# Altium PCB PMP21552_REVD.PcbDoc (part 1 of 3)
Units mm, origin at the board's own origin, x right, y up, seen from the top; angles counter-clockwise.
Board outline 45.05 x 86.02 mm, 4 copper layers (Top Layer, Signal Layer 1, Signal Layer 2, Bottom Layer), stack 1.006 mm thick; 146 components, 80 nets, 395 pads, 82 vias.
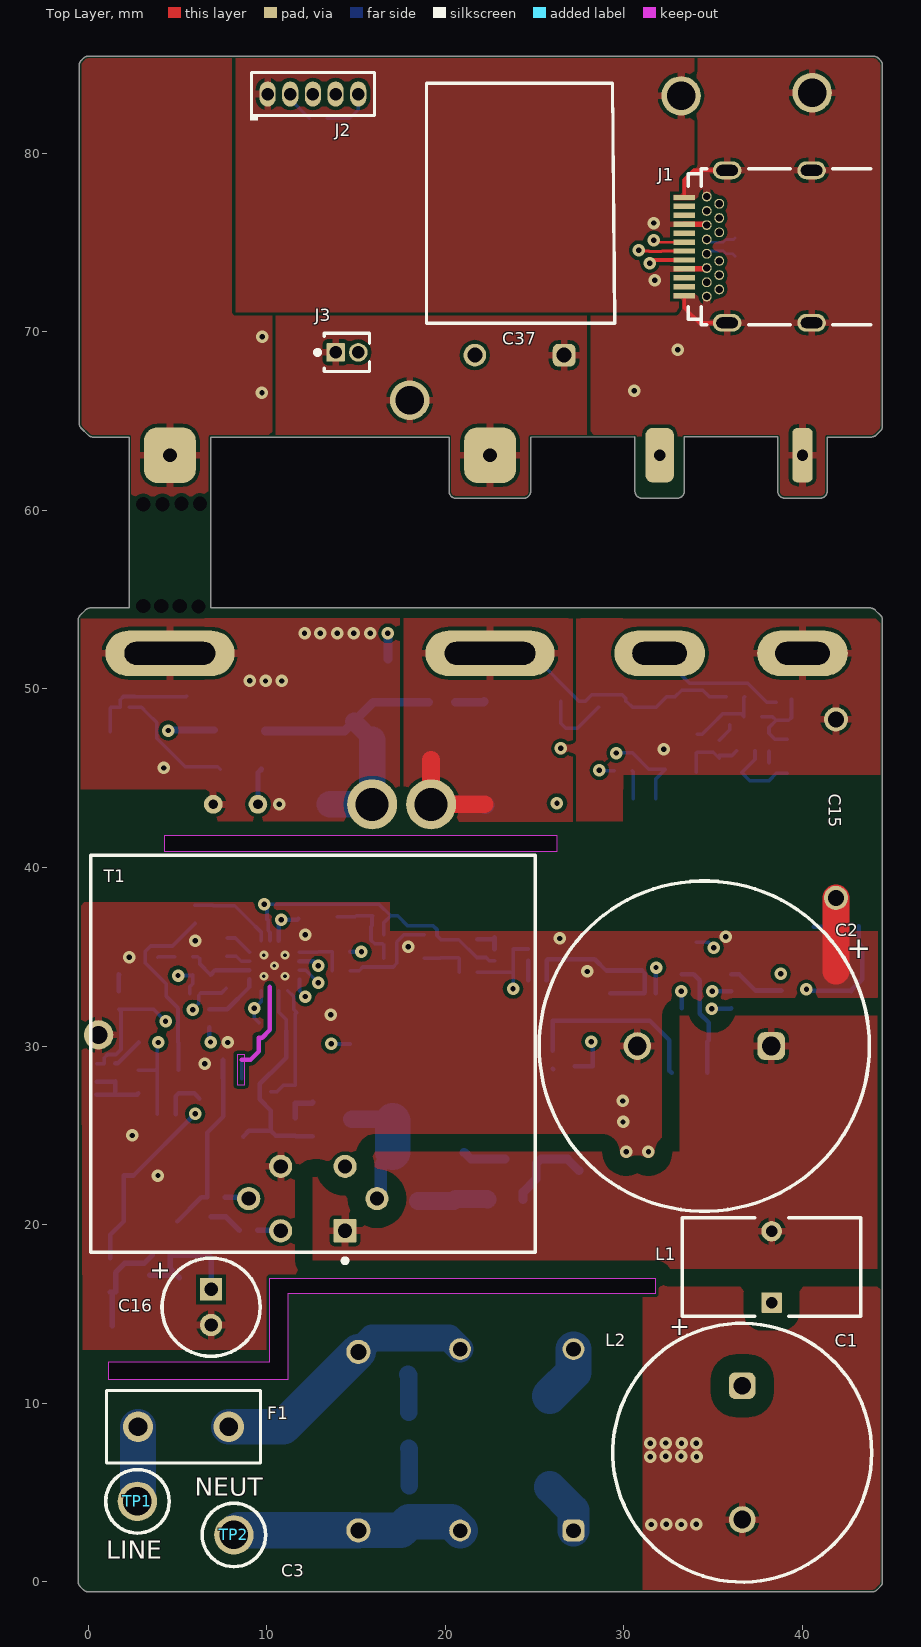
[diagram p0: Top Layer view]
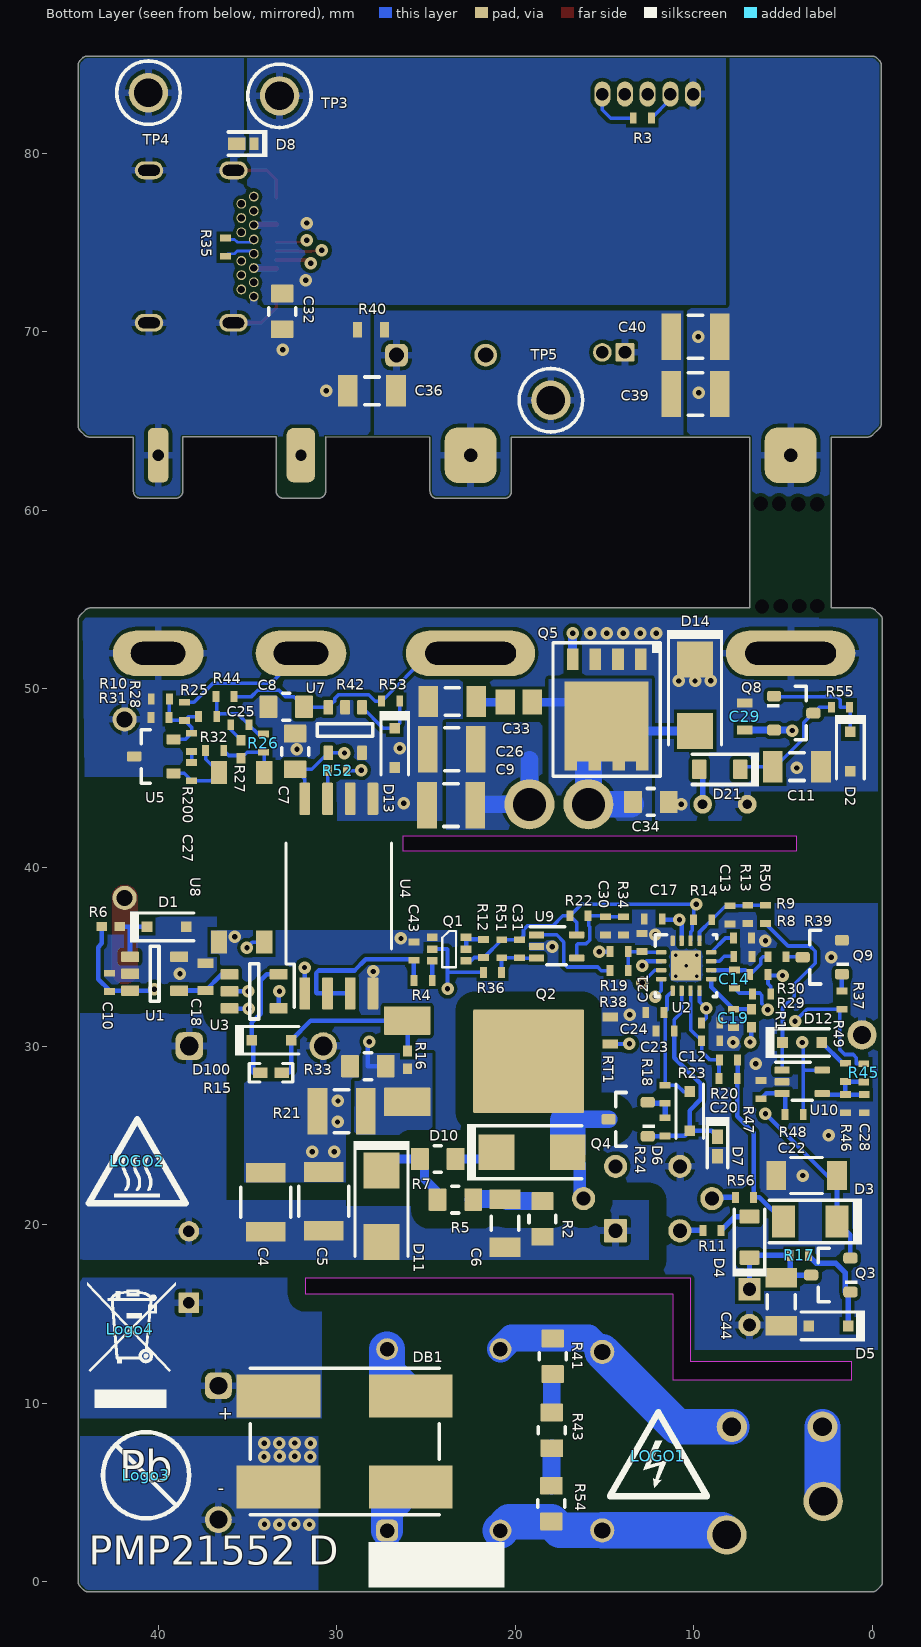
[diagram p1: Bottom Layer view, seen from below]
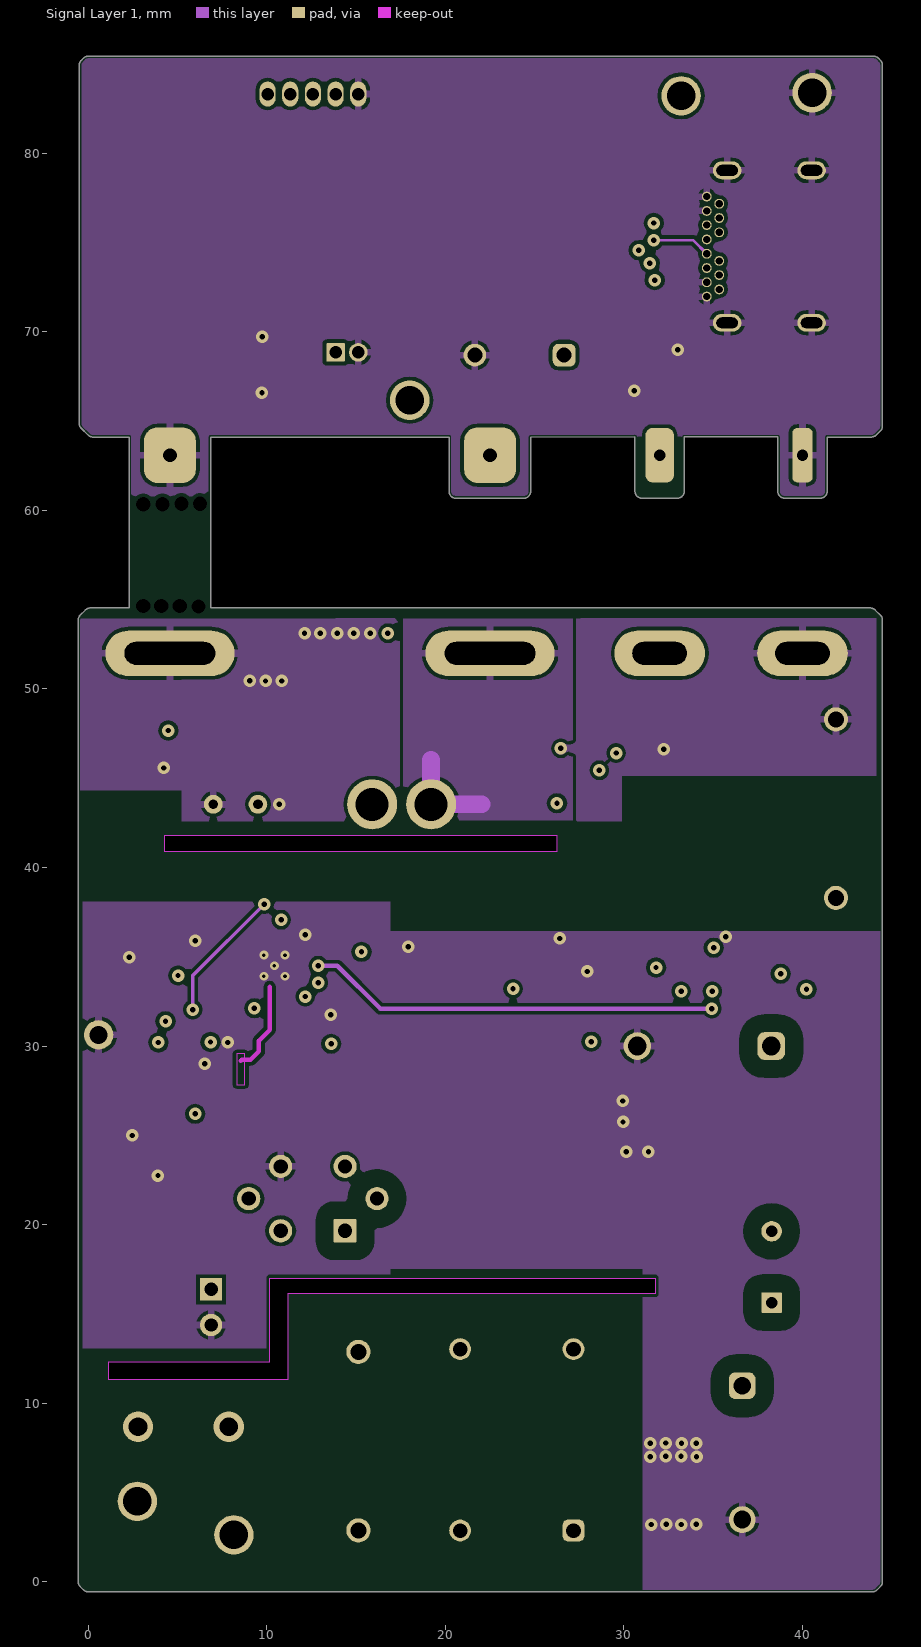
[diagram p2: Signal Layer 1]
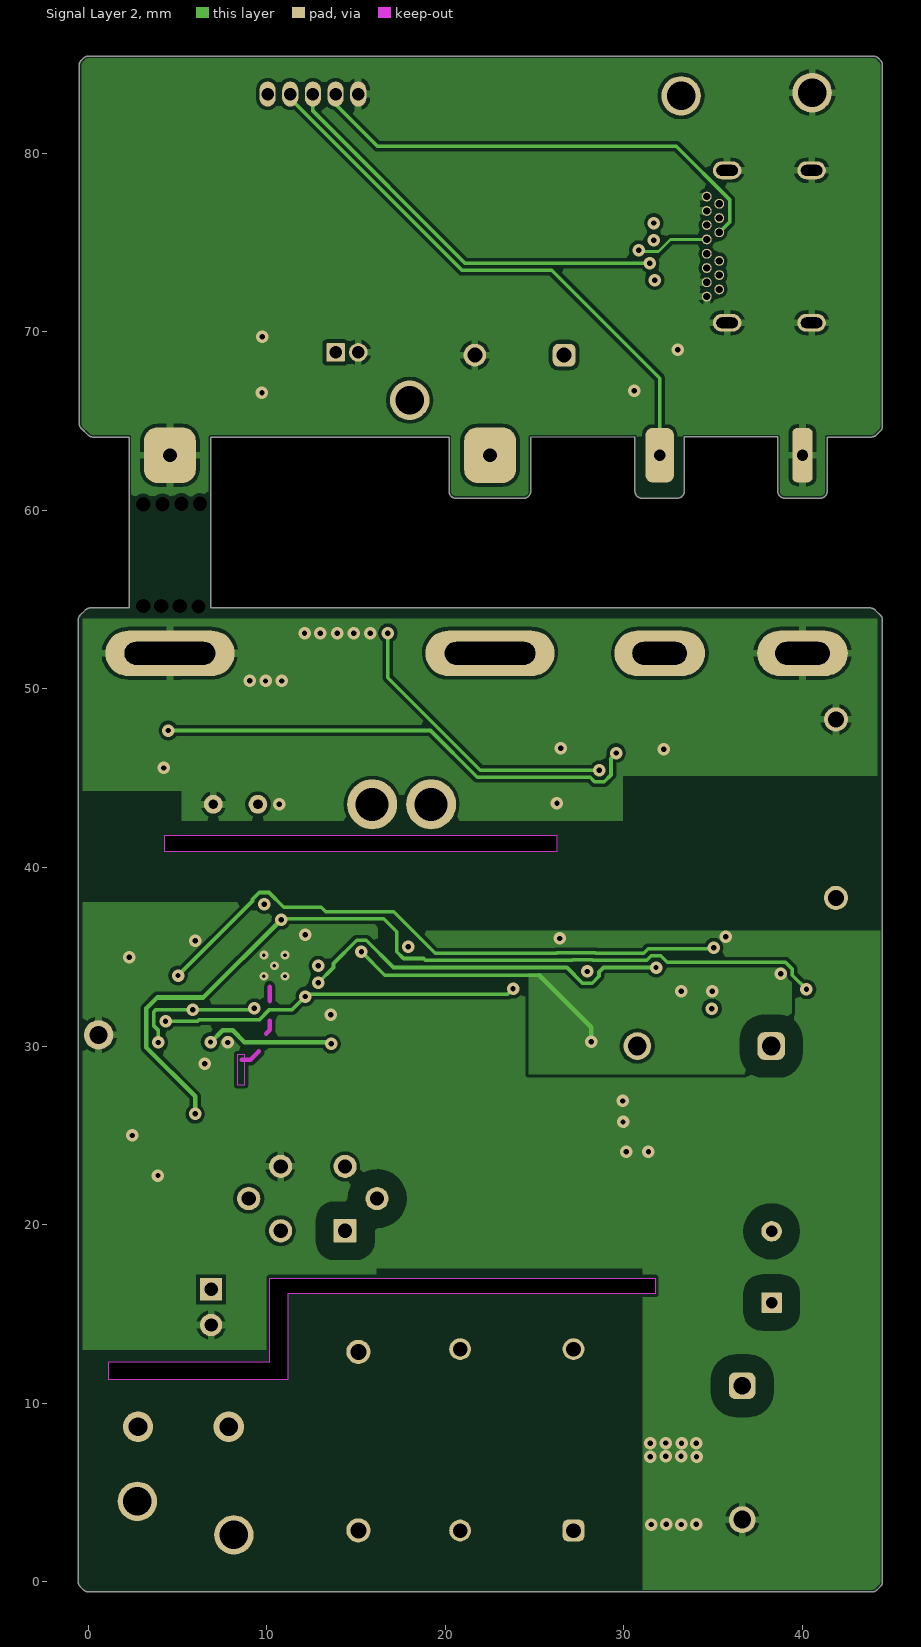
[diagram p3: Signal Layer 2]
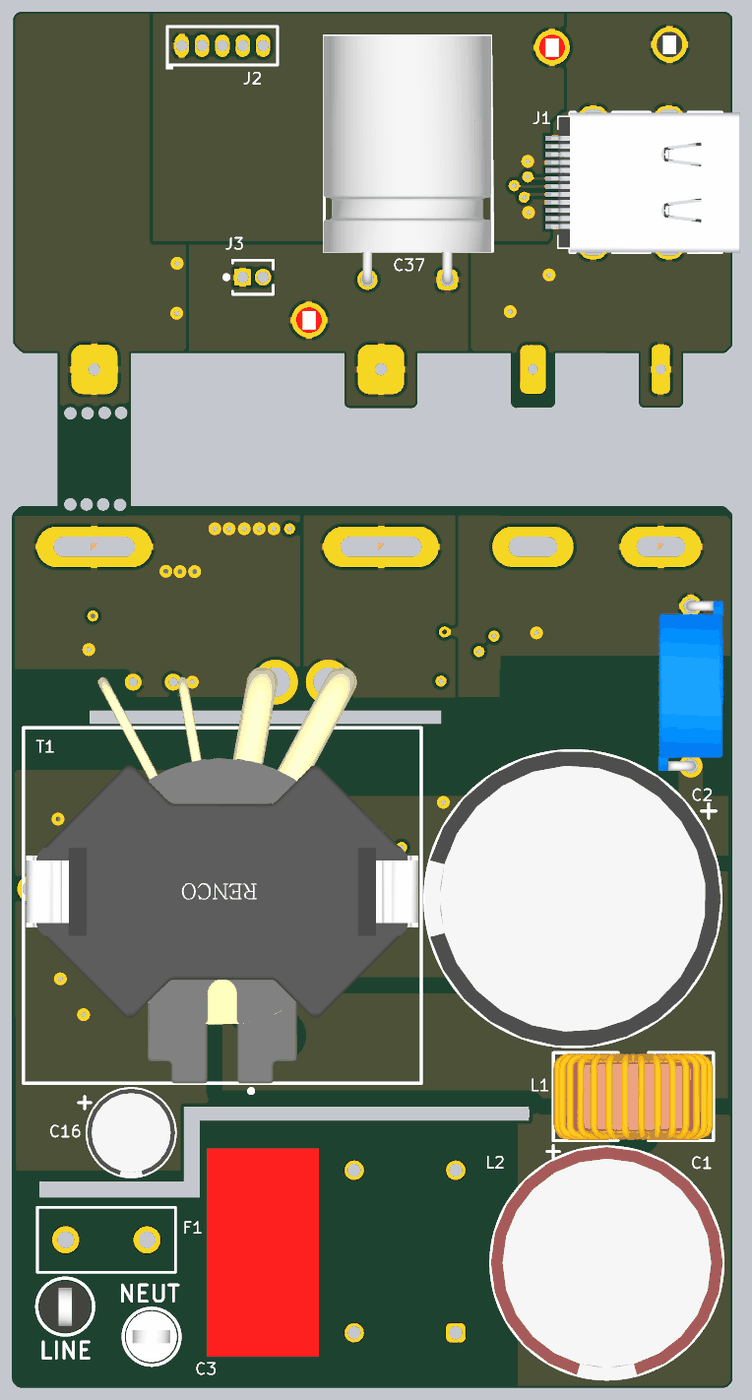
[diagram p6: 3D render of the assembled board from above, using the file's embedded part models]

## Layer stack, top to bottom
Top Solder: solder mask 0.0102, Solder Resist, Dk 3.5
Top Layer: signal copper 0.0356
Dielectric 1: prepreg 0.2032, FR-4, Dk 4.2
Signal Layer 1: signal copper 0.0356
Dielectric 2: core 0.4572, FR-4, Dk 4.2
Signal Layer 2: signal copper 0.0356
Dielectric 3: prepreg 0.2032, FR-4, Dk 4.2
Bottom Layer: signal copper 0.0356
Bottom Solder: solder mask 0.0102, Solder Resist, Dk 3.5

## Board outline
-0.573,0 -0.573,53.858 -0.573,53.862 cw(c-0.191,53.858) -0.463,54.126 -0.461,54.128 -0.16,54.429 -0.159,54.43 cw(c0.11,54.159) 0.11,54.541 2.285,54.541 2.285,64.111 0.254,64.111 cw(c0.254,64.493) -0.014,64.221 -0.016,64.223 -0.397,64.604 -0.399,64.606 cw(c-0.127,64.874) -0.509,64.874 -0.509,84.94 cw(c-0.127,84.94) -0.398,85.209 -0.397,85.21 -0.27,85.337 -0.269,85.338 cw(c0,85.067) 0,85.449 43.973,85.449 cw(c43.973,85.067) 44.242,85.338 44.243,85.337 44.37,85.21 44.371,85.209 cw(c44.1,84.94) 44.482,84.94 44.482,64.734 cw(c44.1,64.734) 44.371,64.466 44.37,64.464 44.128,64.223 44.127,64.221 cw(c43.858,64.493) 43.858,64.111 41.382,64.114 41.382,61.07 cw(c41,61.07) 41,60.688 39,60.688 cw(c39,61.07) 38.618,61.07 38.618,64.117 33.382,64.123 33.382,61.07 cw(c33,61.07) 33,60.688 31.04,60.688 31.023,60.689 cw(c31,61.07) 30.618,61.07 30.618,64.117 24.772,64.111 24.772,61.064 cw(c24.39,61.064) 24.39,60.682 20.59,60.682 cw(c20.59,61.064) 20.208,61.064 20.208,64.111 6.859,64.111 6.859,54.541 43.799,54.541 cw(c43.799,54.159) 44.068,54.431 44.069,54.429 44.37,54.128 44.371,54.127 cw(c44.1,53.858) 44.482,53.858 44.482,0 cw(c44.1,0) 44.371,-0.269 44.37,-0.27 44.179,-0.461 44.178,-0.462 cw(c43.909,-0.191) 43.909,-0.573 0,-0.573 cw(c0,-0.191) -0.269,-0.462 -0.27,-0.461 -0.461,-0.27 -0.462,-0.269 cw(c-0.191,0)
cut-out: 4.264,41.775 4.264,40.925 26.264,40.925 26.264,41.775
cut-out: 1.143,11.303 1.143,12.319 10.16,12.319 10.16,17 31.75,17 31.75,16.125 11.176,16.125 11.176,11.303

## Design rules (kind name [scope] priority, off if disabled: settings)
AcuteAngle [All] p1: minimum=5.00000000000000E+0000 checktracksonly=FALSE
AssemblyTestPointUsage [All] p1: valid=2
BoardOutlineClearance BoardOutlineClearance_MountingHoles [OnCopper and InComponentClass('Mounting Holes')] p1: gap=0.635 ignorepadtopadclearanceinfootprint=FALSE
BoardOutlineClearance BoardOutlineClearance_Poly [OnCopper and InPoly] p2: gap=0.1 ignorepadtopadclearanceinfootprint=FALSE
BoardOutlineClearance [OnCopper and Not InComponentClass('Logo') and not InComponentClass('FiducialMark') and not InRegion(1000,500,4000,800)] p3: gap=0.115 ignorepadtopadclearanceinfootprint=FALSE
Clearance Clearance_HV [InNetClass('HV')] p1: gap=1 ignorepadtopadclearanceinfootprint=TRUE // 1mm Clearance
Clearance Clearance_Keepouts [((IsTrack Or IsArc) And Not InPoly) And IsFree and IsKeepOut vs ((IsTrack Or IsArc) And Not InPoly) And IsFree and IsKeepOut] p2: gap=0 ignorepadtopadclearanceinfootprint=FALSE
Clearance Clearance_Poly [InPolygon] p3: gap=0.203 ignorepadtopadclearanceinfootprint=FALSE except(0: Arc-Hole Track-Hole SMDPad-Hole THPad-Hole Via-Hole Fill-Hole Poly-Hole Region-Hole Text-Hole)
Clearance [All] p4: gap=0.2 ignorepadtopadclearanceinfootprint=FALSE except(0: Arc-Hole Track-Hole SMDPad-Hole THPad-Hole Via-Hole Fill-Hole Poly-Hole Region-Hole Text-Hole)
ComponentClearance ComponentClearance_MountingHoles_FiducialMarks [InComponentClass('Mounting Holes') vs InComponentClass('FiducialMark')] p1: gap=1.27 collisioncheckmode=3 verticalgap=0.254 showdistances=FALSE
ComponentClearance ComponentClearance_Shunt [InComponentClass('Header') vs InComponentClass('Shunt')] p2: gap=0 collisioncheckmode=3 verticalgap=0 showdistances=FALSE
ComponentClearance ComponentClearance_Logo [InComponentClass('Logo')] p3: gap=1.27 collisioncheckmode=3 verticalgap=0.254 showdistances=FALSE
ComponentClearance ComponentClearance_ScrewToNut [(HasFootprint('NY PMS 440 0025 PH')) vs (HasFootprint('Keystone_1902C'))] p4: gap=0.127 collisioncheckmode=3 verticalgap=0.254 showdistances=FALSE
ComponentClearance ComponentClearance_MountingHoles [InComponentClass('Mounting Holes')] p5: gap=6.35 collisioncheckmode=3 verticalgap=2540 showdistances=FALSE
ComponentClearance ComponentClearance_SmallPassives [HasFootprint('0201*') or HasFootprint('0402*') or HasFootprint('0508') or HasFootprint('0603*') or HasFootprint('0612') or HasFootprint('0805*') or HasFootprint('0815*') or HasFootprint('0830*') or HasFootprint('1206*') or HasFootprint('1210*') or HasFootprint('1808*') or HasFootprint('1812*') or HasFootprint('1825*') or HasFootprint('2010*') or HasFootprint('2220*') or HasFootprint('2225*') or HasFootprint('2512*') or HasFootprint('2728*') or HasFootprint('3518*') vs HasFootprint('0201*') or HasFootprint('0402*') or HasFootprint('0508') or HasFootprint('0603*') or HasFootprint('0612') or HasFootprint('0805*') or HasFootprint('0815*') or HasFootprint('0830*') or HasFootprint('1206*') or HasFootprint('1210*') or HasFootprint('1808*') or HasFootprint('1812*') or HasFootprint('1825*') or HasFootprint('2010*') or HasFootprint('2220*') or HasFootprint('2225*') or HasFootprint('2512*') or HasFootprint('2728*') or HasFootprint('3518*')] p6: gap=0.38 collisioncheckmode=3 verticalgap=0.254 showdistances=FALSE
ComponentClearance ComponentClearance_THtoSMT [IsThruComponent vs IsSMTComponent] p7: gap=0.381 collisioncheckmode=3 verticalgap=0.762 showdistances=FALSE
ComponentClearance ComponentClearance_THtoTH [IsThruComponent vs IsThruComponent] p8: gap=0.381 collisioncheckmode=3 verticalgap=0.762 showdistances=FALSE
ComponentClearance [All] p9: gap=0.381 collisioncheckmode=3 verticalgap=0.254 showdistances=FALSE
DiffPairsRouting [All] p1: maxlimit=2.54 minlimit=0.254 mostfreqgap=0.254 toplayer_minwidth=0.381 toplayer_maxwidth=0.381 toplayer_prefwidth=0.381 midlayer1_minwidth=0.381 midlayer1_maxwidth=0.381 midlayer1_prefwidth=0.381 midlayer2_minwidth=0.381 midlayer2_maxwidth=0.381 midlayer2_prefwidth=0.381 bottomlayer_minwidth=0.381 bottomlayer_maxwidth=0.381 bottomlayer_prefwidth=0.381 maxuncoupledlength=25.4
FabricationTestPointUsage TestPointUsage [All] p1: valid=2 allowmultiple=FALSE
FabricationTestpoint Testpoint [All] p1: side=3 testpointundercomponent=TRUE minsize=1.016 maxsize=2.54 preferedsize=1.524 minholesize=0 maxholesize=1.016 preferedholesize=0.813 testpointgrid=0.025 allowsidetop=TRUE allowsidebottom=TRUE usegrid=TRUE gridtolerance=0
FanoutControl Fanout_LCC [IsLCC] p1: bgadir=Out bgaviamode=Centered fanoutstyle=Auto fanoutdirection=Alternating viagrid=0.025 // Fanout_LCC (Default Rule)
FanoutControl Fanout_BGA [IsBGA] p2: bgadir=Out bgaviamode=Centered fanoutstyle=Auto fanoutdirection=Alternating viagrid=0.025 // Fanout_BGA (Default Rule)
FanoutControl Fanout_Default [All] p4: bgadir=Out bgaviamode=Centered fanoutstyle=Auto fanoutdirection=Alternating viagrid=0.025 // Fanout_Default (Default Rule)
FanoutControl Fanout_Small [(CompPinCount < 5)] p5: bgadir=Out bgaviamode=Centered fanoutstyle=Auto fanoutdirection=OutThenIn viagrid=0.025 // Fanout_Small (Default Rule)
HoleSize [All] p1: absolutevalues=TRUE maxlimit=6.375 minlimit=0.2 maxpercent=80.000 minpercent=20.000
HoleToHoleClearance [All] p1: gap=0.2 allowstackedmicrovias=TRUE
MinimumAnnularRing MinimumAnnularRing_ThermalPadVias [IsVia and InAnyComponent] p1: minimumring=0.15
MinimumAnnularRing [All] p2: minimumring=0.15
MinimumSolderMaskSliver MinimumSolderMaskSliver_Logo [InComponentClass('Logo') vs InComponentClass('Logo')] p1: minsoldermaskwidth=0.018
MinimumSolderMaskSliver [All] p2: minsoldermaskwidth=0.025
PlaneConnect [All] p1: planeconnectstyle=Direct reliefexpansion=0.254 reliefentries=4 reliefconductorwidth=0.254 reliefairgap=0.254
PolygonConnect [All] p1: thpad.connectstyle=Relief thpad.reliefconductorwidth=0.4 thpad.reliefentries=4 thpad.polygonreliefangle="90 Angle" thpad.airgapwidth=0.2 smdpad.connectstyle=Direct smdpad.reliefconductorwidth=0.254 smdpad.reliefentries=4 smdpad.polygonreliefangle="90 Angle" smdpad.airgapwidth=0.254 via.connectstyle=Direct via.reliefconductorwidth=0.254 via.reliefentries=4 via.polygonreliefangle="90 Angle" via.airgapwidth=0.254
RoutingVias ThermalPadVias [IsVia and InAnyComponent] p1: holewidth=0.2 width=0.5 viastyle="Through Hole" minholewidth=0.2 minwidth=0.5 maxholewidth=0.33 maxwidth=0.6
RoutingVias [All] p2: holewidth=0.406 width=0.864 viastyle="Through Hole" minholewidth=0.2 minwidth=0.66 maxholewidth=1.016 maxwidth=1.651
SilkToBoardRegionClearance [Not ((IsComment or IsDesignator) And (Hide <> 'False')) and not InRegion(1000,500,4000,800)] p1:
SilkToSilkClearance SilkToSilkClearance_Pb-FreeLogo [(HasFootprint('Pb-Free_Overlay_Medium') OR HasFootprint('Pb-Free_Overlay_Small')) vs (HasFootprint('Pb-Free_Overlay_Medium') OR HasFootprint('Pb-Free_Overlay_Small'))] p1: silktosilkclearance=0
SilkToSilkClearance [All] p2: silktosilkclearance=0.025
SilkToSolderMaskClearance SilkToComponentPadClearance [IsPad and InAnycomponent] p1: minsilkscreentomaskgap=0 clearancetoexposedcopper=TRUE
SilkToSolderMaskClearance "Silk to Solder Mask Opening" [All] p2: minsilkscreentomaskgap=0 clearancetoexposedcopper=FALSE
SolderMaskExpansion [All] p1: expansion=0.05
Width [All] p1: maxlimit=2.54 minlimit=0.152 preferedwidth=0.254 checkconnectedcopper=TRUE
14 further rules are at their usual default settings.

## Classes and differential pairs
net class Secondary: SGND
net class Primary: PGND
net class HV: NetC1_1 NetC6_2 NetD10_1 NetD11_1 Vbulk Vswn
component class Header: J2 J3
component class PMP21552_REVD_Secondary: C32 C36 C37 C39 C40 D8 J1 J2 J3 R3 R35 R40 TP3 TP4 TP5
component class PMP21552_REVD_Primary: C1 C2 C3 C4 C5 C6 C7 C8 C9 C10 C11 C12 C13 C14 C15 C16 C17 C18 C19 C20 C21 C22 C23 C24 C25 C26 C27 C28 C29 C30 C31 C33 C34 C43 C44 C? D1 D2 D3 D4 D5 D6 D7 D10 D11 D12 D13 D14 D21 D100 D? DB1 F1 L1 L2 LOGO1 LOGO2 Logo3 Logo4 Q1 Q2 Q3 Q4 Q5 Q8 Q9 Q? R1 R2 R4 R5 R6 R7 R8 R9 R10 R11 R12 R13 R14 R15 R16 R17 R18 R19 R20 R21 R22 R23 R24 R25 R26 R27 R28 R29 R30 R31 R32 R33 R34 R36 R37 R38 R39 R41 R42 R43 R44 R45 R46 R47 R48 R49 R50 R51 R52 R53 R54 R55 R56 R200 R? RT1 T1 TP1 TP2 TP? U1 U2 U3 U4 U5 U7 U8 U9 U10 U?

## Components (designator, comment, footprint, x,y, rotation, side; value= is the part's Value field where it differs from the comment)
C1 "EKXJ401ELL390MU20S" Chemi-Con_1450x2000 36.625,7.225 r270 top value=39uF
C2 "400BXW68MEFC18X20" BXW_1800x2000 34.5,30 r180 top value=68uF
C3 "890324023023" WCAP-FTX2_1300x700x1300 15.125,7.875 r270 top value=0.1uF
C4 "C1210C104KBRAC7800" 1210_280 33.975,21.25 r270 bottom value=0.1uF
C5 "C1210C104KBRAC7800" 1210_280 30.725,21.3 r270 bottom value=0.1uF
C6 "GRM31BR72J102KW01L" 1206L 20.575,20.075 r90 bottom value=1000pF
C7 "CGA4J3X7R1E225K125AB" 0805_HV1 32.325,46.502 r90 bottom value=2.2uF
C8 "C2012X7R1H105K085AC" 0805_HV1 32.825,49 r0 bottom value=1uF
C9 "GRM32ER71E226KE15L" 1210_270L 23.59,43.5 r0 bottom value=22uF
C10 "GRM155R71H104ME14D" 0402S 42.725,33.567 r90 bottom value=0.1uF
C11 "C3216X7R2A105M160AA" 1206L 4.225,45.65 r180 bottom value=1uF
C12 "C1005X7R1H104K050BB" 0402S 9.05,31.3 r180 bottom value=0.1uF
C13 "GRM1555C1H101JA01D" 0402S 7.975,37.35 r90 bottom value=100pF
C14 "GRM1555C1H101JA01D" 0402S 7.725,33.75 r270 bottom value=100pF
C15 "DE1E3RA222MN4AN01F" DE1_900x400 41.875,43.3 r270 top value=2200pF
C16 "UPS2A4R7MDD1TD" UPW_500x1100 6.875,15.375 r270 top value=4.7uF
C17 "GRM155R71H104ME14D" 0402S 12.267,37.125 r0 bottom value=0.1uF
C18 "C1608X7R1E105K080AB" 0603S 37.35,33.875 r270 bottom value=1uF
C19 "GRM1555C1H101JA01D" 0402S 7.774,31.55 r90 bottom value=100pF
C20 "GRM1555C1H3R3CA01D" 0402S 8.075,28.175 r0 bottom value=3.3pF
C21 "GRM1555C1H101JA01D" 0402S 12.9,35.8 r270 bottom value=100pF
C22 "C3216X5R1H106K160AB" 1206_180 3.675,22.75 r0 bottom value=10uF
C23 "GRM155R71H222KA01D" 0402S 11.6,30.85 r0 bottom value=2200pF
C24 "GRM1555C1H240JA01D" 0402S 12.175,31.875 r180 bottom value=24pF
C25 "GRM155R71H183KA12D" 0402S 35.425,47.999 r0 bottom value=0.018uF
C26 "GRM32ER71E226KE15L" 1210_270L 23.55,46.625 r0 bottom value=22uF
C27 "GRM155R71H472KA01D" 0402S 38.125,45.373 r270 bottom value=4700pF
C28 "GRM155R71H102KA01D" 0402S 0.45,26.775 r270 bottom value=1000pF
C29 "C1608X7R1E105K080AB" 0603S 7.139,48.458 r270 bottom value=1uF
C30 "GRM155R71H102KA01D" 0402S 14.95,36.733 r270 bottom value=1000pF
C31 "GRM155R71H222KA01D" 0402S 19.75,35.45 r270 bottom value=2200pF
C32 "GRM21BR6YA106KE43L" 0805_HV1 33.05,71.15 r270 bottom value=10uF
C33 "GRM21AR72E102KW01D" 0805L 19.8,49.258 r180 bottom value=1000pF
C34 "GRM21AR72E152KW01D" 0805_HV1 12.4,43.675 r180 bottom value=1500pF
C36 "GRM31MR71H224KA01L" 1206L 28.025,66.7 r0 bottom value=0.22uF
C37 "687AVG025MGBJ" AVG_1000X1200_HD 24.15,68.7 r180 top value=680uF
C39 "GRM32ER71E226KE15L" 1210_270L 9.9,66.525 r180 bottom value=22uF
C40 "GRM32ER71E226KE15L" 1210_270L 9.9,69.725 r180 bottom value=22uF
C43 "GRM155R71H103KA88D" 0402S 25.675,35.315 r270 bottom value=0.01uF
C44 "12061C104JAT2A" 1206L 5.1,15.675 r270 bottom value=0.1uF
D1 "MMSZ5240BS-7-F" SOD-323 39.525,36.675 r180 bottom value=10V
D2 "BZT52C9V1S-7-F" SOD-323 1.225,46.5 r270 bottom value=9.1V
D3 "CSFMT104-HF" SOD-123H 3.475,20.175 r0 bottom value=200V
D4 "RFU02VSM8STR" TUMD2SM 6.875,19.3 r90 bottom value=800V
D5 "MMSZ5245BS-7-F" SOD-323 2.45,14.325 r0 bottom value=15V
D6 "CDSOD323-T18C" SOD-323-Bi 10.225,26.35 r270 bottom value=18V
D7 "BZT52C22T-7" SOD-523 8.667,24.375 r270 bottom value=22V
D8 "NSR20F30NXT5G" DSN2_0603 35.275,80.55 r0 bottom value=30V
D10 "MRA4007T3G" SMA 19.05,24.05 r180 bottom value=1000V
D11 "SMAJ150A" SMA 27.483,21.025 r270 bottom value=150V
D12 "BAS316,115" SOD-323 3.925,30.2 r180 bottom value=100V
D13 "MMSZ5240BS-7-F" SOD-323 26.75,46.7 r270 bottom value=10V
D14 "SMAJ100CA" SMA 9.925,49.65 r270 bottom value=100V
D21 "RFU02VSM8STR" TUMD2SM 8.542,45.502 r0 bottom value=800V
D100 "BAS316,115" SOD-323 33.65,30.325 r180 bottom value=100V
DB1 "Z4DGP406L-HF" Z4-D 29.55,7.855 r180 bottom value=600V
F1 "39213150000" FUSE_392 5.325,8.675 r180 top
J1 "632 723 300 011" Wurth_632_723_300_011 43.96,74.78 r90 top
J2 "GRPB051VWVN-RC" Sullins_GRPB051VWVN-RC 12.58,83.325 r0 top locked
J3 "GRPB021VWVN-RC" Sullins_GRPB021VWVN-RC 14.487,68.855 r0 top locked
L1 "7447052" FP-7447052_PTH_D10MM0-MFG 38.275,17.625 r180 top
L2 "RLTI-1301" Renco_RLTI-1301 24,7.945 r180 top value=1.3mH
LOGO1 "DANGER HIGH VOLTAGE" IEC_HighVoltage_Small 11.975,7.016 r180 bottom
LOGO2 "CAUTION HOT SURFACE" IEC_HotSurface_Small 41.175,23.55 r180 bottom
Logo3 "Pb-Free Symbol" Pb-Free_Overlay_Medium 40.675,5.961 r180 bottom
Logo4 "WEEE logo" WEEE_Minimum 41.55,14.125 r180 bottom
Q1 "SI1553CDL-T1-GE3" SOT-363 23.7,35.434 r180 bottom value=20V
Q2 "IPD60R280P7SAUMA1" DPAK 22.65,29.15 r180 bottom value=600V
Q3 "BSS123" SOT-23L 2.325,17.175 r0 bottom value=100V
Q4 "BSS126H6327XTSA2" SOT-23L 13.675,25.9 r0 bottom value=600V
Q5 "BSC093N15NS5ATMA1" PG-TDSON-8 14.875,48.85 r270 bottom value=150V
Q8 "BSS123" SOT-23L 4.4,48.65 r180 bottom value=100V
Q9 "FDV301N" SOT-23L 2.8,34.977 r0 bottom value=25V
R1 "CRCW04027K50FKED" 0402L 6.775,31.556 r270 bottom value=7.50k
R2 "CRCW0805470KJNEA" 0805_HV1 18.475,20.316 r270 bottom value=470k
R3 "CRCW040215K0FKED" 0402S 12.875,81.975 r180 bottom value=15.0k
R4 "CRCW0402100RJNED" 0402S 25.153,33.677 r180 bottom value=100
R5 "CRCW080515R0JNEA" 0805_HV1 23.35,21.4 r180 bottom value=15
R6 "RC0402FR-07100KL" 0402L 42.65,36.7 r0 bottom value=100k
R7 "CRCW080515R0JNEA" 0805_HV1 24.34,23.675 r0 bottom value=15
R8 "CRCW0402200KFKED" 0402S 7.25,35.025 r0 bottom value=200k
R9 "CRCW040275K0FKED" 0402S 7.266,36.05 r180 bottom value=75.0k
R10 "CRCW040226K7FKED" 0402S 39.875,49.431 r0 bottom value=26.7k
R11 "CRCW04020000Z0ED" 0402S 8.975,19.675 r180 bottom value=0
R12 "RC0402FR-07100KL" 0402S 21.775,35.466 r90 bottom value=100k
R13 "CRCW040230K1FKED" 0402S 6.975,37.375 r90 bottom value=30.1k
R14 "CRCW0402200KFKED" 0402S 9.5,37.075 r0 bottom value=200k
R15 "CRCW0402100RFKED" 0402 33.675,28.5 r180 bottom value=100
R16 "CRCW040210K0JNED" 0402L 26.025,29.225 r90 bottom value=10k
R17 "CRCW0402200KFKED" 0402S 4.083,18.275 r180 bottom value=200k
R18 "CRCW0402511RFKED" 0402S 11.6,27.3 r270 bottom value=511
R19 "CRCW0402750RFKED" 0402S 14.175,35.292 r0 bottom value=750
R20 "CRCW040256K2FKED" 0402S 8.05,29.225 r180 bottom value=56.2k
R21 "MCR25JZHFLR220" 1210L 29.725,26.35 r180 bottom value=0.22
R22 "CRCW04021M00JNED" 0402S 16.425,37.3 r0 bottom value=1.0Meg
R23 "CRCW040213K3FKED" 0402S 9.05,30.3 r0 bottom value=13.3k
R24 "CRCW04021M00JNED" 0402S 11.6,25.475 r270 bottom value=1.0Meg
R25 "ERJ-2RKF1503X" 0402S 37.225,48.45 r180 bottom value=150k
R26 "CRCW04023K01FKED" 0402S 34.1,46.968 r90 bottom value=3.01k
R27 "CRCW0402681RFKED" 0402L 35.349,46.625 r90 bottom value=681
R28 "CRCW040224K9FKED" 0402S 38.525,48.75 r270 bottom value=24.9k
R29 "CRCW04021M00JNED" 0402S 6.198,32.925 r0 bottom value=1.0Meg
R30 "CRCW040220K0FKED" 0402S 6.35,34 r180 bottom value=20.0k
R31 "ERJ-2RKF1503X" 0402S 39.892,48.4 r0 bottom value=150k
R32 "CRCW040215K0FKED" 0402S 36.832,46.551 r180 bottom value=15.0k
R33 "RC0805FR-071R5L" 0805_HV1 28.25,28.875 r0 bottom value=1.50
R34 "CRCW04021M00JNED" 0402S 13.938,36.733 r270 bottom value=1.0Meg
R35 "CRCW0402100RJNED" 0402S 36.225,74.75 r90 bottom value=100
R36 "CRCW0402475KFKED" 0402S 21.275,34.125 r180 bottom value=475k
R37 "RC0402JR-070RL" 0402S 1.7,32.575 r270 bottom value=0
R38 "CRCW0402511RFKED" 0402S 14.175,34.225 r180 bottom value=511
R39 "CRCW0402475KFKED" 0402S 5.335,35 r0 bottom value=475k
R40 "CRCW060310M0JNEA" 0603S 28.075,70.125 r180 bottom value=10Meg
R41 "CRCW08055M10JNEA" 0805_HV1 17.9,12.625 r90 bottom value=5.1Meg
R42 "RC0402FR-07100KL" 0402S 26.975,49.317 r180 bottom value=100k
R43 "CRCW08055M10JNEA" 0805_HV1 17.95,8.475 r90 bottom value=5.1Meg
R44 "RC0402JR-070RL" 0402S 36.25,49.575 r0 bottom value=0
R45 "CRCW0402301KFKED" 0402S 0.475,28.5 r270 bottom value=301k
R46 "RC0402FR-07100KL" 0402S 1.5,26.775 r270 bottom value=100k
R47 "RC0402FR-07100KL" 0402S 6.225,27.558 r90 bottom value=100k
R48 "CRCW0402392KFKED" 0402S 4.376,26.175 r180 bottom value=392k
R49 "CRCW0402267KFKED" 0402S 1.5,28.525 r90 bottom value=267k
R50 "CRCW040290K9FKED" 0402S 5.975,37.375 r90 bottom value=90.9k
R51 "CRCW04022M21FKED" 0402S 20.75,35.452 r90 bottom value=2.21Meg
R52 "CRCW04021R00JNED" 0402S 29.95,45.425 r180 bottom value=1.0
R53 "CRCW120610R0JNEA" 1206L 23.525,49.3 r180 bottom value=10
R54 "CRCW08055M10JNEA" 0805_HV1 17.975,4.375 r90 bottom value=5.1Meg
R55 "CRCW04021M00JNED" 0402S 1.775,48.975 r180 bottom value=1.0Meg
R56 "CRCW04024R70JNED" 0402S 7.158,21.525 r0 bottom value=4.7
R200 "CRCW040261K9FKED" 0402S 38.125,47.014 r90 bottom value=61.9k
RT1 "NCP18WB473J03RB" 0603S 14.675,30.875 r90 bottom value=47k
T1 "RLTI-1324" FP-RLTI-1324_PTH_0IN980_0IN766-MFG 12.575,29.572 r180 top
TP1 "LINE" Keystone5011 2.75,4.5 r0 top
TP2 "NEUTRAL" Keystone5012 8.153,2.616 r270 top
TP3 "5010" Keystone5010 33.2,83.225 r180 bottom
TP4 "SGND" Keystone5011 40.542,83.4 r180 bottom
TP5 "5010" Keystone5010 18,66.175 r180 bottom
U1 "TPS7B4250QDBVRQ1" DBV0005A_N 40.2,34.05 r180 bottom
U2 "UCC28780RTER" RTE0016C 10.425,34.5 r180 bottom
U3 "UCC27517DBVR" DBV0005A_N 34.625,33.067 r180 bottom
U4 "UCC5304DWV" DWV0008A 29.875,38.4 r90 bottom
U5 "ATL431AIDBZR" DBZ0003A_L 40.242,46.225 r0 bottom
U7 "TPS7B4250QDBVRQ1" DBV0005A_L 29.525,47.7 r270 bottom
U8 "VOL618A-2T" SOP254P1020X230-4 35.325,40.575 r270 bottom
U9 "TLV7021DCKR" DCK0005A_N 17.681,35.578 r180 bottom
U10 "TLV7021DCKR" DCK0005A_N 3.925,28 r180 bottom

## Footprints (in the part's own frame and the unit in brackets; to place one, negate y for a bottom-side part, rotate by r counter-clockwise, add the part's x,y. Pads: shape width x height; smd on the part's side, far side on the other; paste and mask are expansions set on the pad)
0402 [mm] "0402 from SM-752 data"
  rect 0.8x0.6 smd: 1(-0.6,0) 2(0.6,0)
  silkscreen extent -1.22,-0.52 1.22,0.52, body extent -0.55,-0.3 0.55,0.3, height 0.6
0402L [mm] "0402 from SM-752 data"
  rect 0.6x0.5 smd: 1(-0.5,0) 2(0.5,0)
  body extent -0.55,-0.3 0.55,0.3, height 0.6
0402S [mil] "Based on C0402S footprint from PADS legacy"
  rect 15x24 smd: 1(-20,0) 2(20,0)
  body extent -22,-12 22,12, height 24
0603S [mil]
  rect 20x35 smd: 1(-30,0) 2(30,0)
  body extent -34,-19 34,19, height 39
0805_HV1 [mm] "Custom footprint based on analyzing multiple manufacturer recommendations"
  rrect10% 1x1.25 smd: 1(-1,0) 2(1,0)
  silkscreen extent -0.2,-0.75 0.2,0.75, body extent -1.1,-0.72 1.1,0.73, height 1.45
0805L [mm] "0805 from SM-752 data"
  rect 1.1x1.4 smd: 1(-0.75,0) 2(0.75,0)
  body extent -1.1,-0.72 1.1,0.72, height 1.45
1206_180 [mm] "1206_180"
  rect 1.1x1.6 smd: 1(-1.7,0) 2(1.7,0)
  silkscreen extent -0.9,-1 0.9,1, body extent -1.75,-0.95 1.75,0.95, height 1.8
1206L [mm] "1206 from SM-752 data"
  rect 1.1x1.75 smd: 1(-1.35,0) 2(1.35,0)
  silkscreen extent -0.4,-0.77 0.4,0.77, body extent -1.7,-0.9 1.7,0.9, height 1.35
1210_270L [mm] "1210"
  rect 1.1x2.6 smd: 1(-1.35,0) 2(1.35,0)
  silkscreen extent -0.4,-1.2 0.4,1.2, body extent -1.7,-1.35 1.7,1.35, height 2.7
1210_280 [mm] "SMD, 2-Leads, Body 3.6x2.8mm, Height 2.8mm"
  rect 1.1x2.2 smd: 1(-1.65,0) 2(1.65,0)
  silkscreen extent -0.84,-1.4 0.84,1.4, body extent -1.8,-1.4 1.8,1.4, height 2.8
1210L [mm] "1210 from SM-752 data"
  rect 1.1x2.6 smd: 1(-1.35,0) 2(1.35,0)
  silkscreen extent -0.4,-1.2 0.4,1.2, body extent -1.7,-1.35 1.7,1.35, height 1.35
AVG_1000X1200_HD [mm] "TH, 2-Leads, Dia 10mm, Pin Spacing 5mm"
  rrect50% 1.275x1.275 hole 0.85: 1(-2.5,0)
  round 1.275 hole 0.85: 2(2.5,0)
  silkscreen extent -5.33,-15.24 5.21,-1.78, body extent -5.25,-15.25 5.25,0.31, height 10.5
BXW_1800x2000 [mm] "TH, 2-Leads, Dia 18mm, Pin Spacing 7.5mm"
  rrect50% 1.55x1.55 hole 1.05: 1(-3.75,0)
  round 1.55 hole 1.05: 2(3.75,0)
  silkscreen extent -9.25,-9.25 9.25,9.25, body extent -9.25,-9.25 9.26,9.25, height 22.01
Chemi-Con_1450x2000 [mm] "TH, 2-Leads, Dia 14.5mm"
  rrect50% 1.5x1.5 hole 1: 1(-3.75,0)
  round 1.5 hole 1: 2(3.75,0)
  silkscreen extent -7.25,-7.25 7.25,7.25, body extent -7.25,-7.25 7.26,7.25, height 21.51
DBV0005A_L [mm] "SOT23, 5-Leads, Body 2.9x1.6mm, Pitch 0.95mm, Lead Span 2.8mm, IPC High Density"
  rrect18% 0.8x0.55 smd: 1(-1.275,0.95) 2(-1.275,0) 3(-1.275,-0.95) 4(1.275,-0.95) 5(1.275,0.95)
  silkscreen extent -0.35,-1.55 0.35,1.55, body extent -1.42,-1.46 1.42,1.46, height 1.09
DBV0005A_N [mm] "SOT23, 5-Leads, Body 2.9x1.6mm, Pitch 0.95mm, Lead Span 2.8mm, IPC Medium Density"
  rrect17% 1x0.6 smd: 1(-1.375,0.95) 2(-1.375,0) 3(-1.375,-0.95) 4(1.375,-0.95) 5(1.375,0.95)
  silkscreen extent -0.25,-1.55 0.25,1.55, body extent -1.42,-1.46 1.42,1.46, height 1.09
DBZ0003A_L [mm] "SOT23, 3-Leads, Body 2.9x1.3mm, Pitch 0.95mm, Lead Span 2.4mm, IPC High Density"
  rrect18% 0.8x0.55 smd: 1(-1.1,0.95) 2(-1.1,-0.95) 3(1.1,0)
  silkscreen extent 0.2,-1.5 0.7,1.5, body extent -1.26,-1.46 1.26,1.46, height 0.98
DCK0005A_N [mm] "SOT353, 5-Leads, Body 2x1.3mm, Pitch 0.65mm, Lead Span 2.1mm, IPC Medium Density"
  rrect25% 0.85x0.4 smd: 1(-1.125,0.65) 2(-1.125,0) 3(-1.125,-0.65) 4(1.125,-0.65) 5(1.125,0.65)
  silkscreen extent -1.48,-1.02 0.55,1.1, body extent -1.14,-1 1.14,1, height 0.95
DE1_900x400 [mm] "TH, 2-Leads, Dia 9mm, Lead Spacing 10mm"
  round 1.35 hole 0.9: 1(-5,0) 2(5,0)
  body extent -5.3,-2 5.3,2, height 11.5
DPAK [mm] "D-PAK, 3-Pads, Body 6.22x6.73mm (max), TO-252AA using nominal STEP model"
  rrect6% 2.6x1.6 smd: 1(-3.4,2.28) 3(-3.4,-2.28)
  rrect2% 6.2x5.8 smd paste-3: 2(3.4,0)
  body extent -3.86,-3.29 5.84,3.29, height 2.48
DSN2_0603 [mm] "SMD, 2-Leads, Body 1.6x0.8mm"
  rect 0.52x0.7 smd paste+0 mask+0.127: 1(-0.64,0)
  rect 0.991x0.7 smd paste+0 mask+0.127: 2(0.318,0)
  silkscreen extent -1.4,-0.75 0.8,0.75, body extent -0.8,-0.4 0.8,0.4, height 0.31
DWV0008A [mm] "SOIC, 8-Leads, Body 5.95x7.6mm (max), Pitch 1.27mm"
  rrect17% 1.8x0.6 smd: 1(-5.45,1.905) 2(-5.45,0.635) 3(-5.45,-0.635) 4(-5.45,-1.905) 5(5.45,-1.905) 6(5.45,-0.635) 7(5.45,0.635) 8(5.45,1.905)
  silkscreen extent -6.25,-2.95 2.98,2.95, body extent -5.77,-2.92 5.77,2.93, height 2.67
FP-7447052_PTH_D10MM0-MFG [mm]
  rrect9% 1.15x1.15 hole 0.65 paste-1000 mask+0: 1(0,2)
  round 1.15 hole 0.65 paste-1000 mask+0: 2(0,-2)
  silkscreen extent -5,-2.75 5,2.75, body extent -5.1,-2.85 5.1,2.85, height 0.25
FP-RLTI-1324_PTH_0IN980_0IN766-MFG [mm]
  rrect8% 1.3x1.3 hole 0.8 paste-1000 mask+0: 1(-1.803,9.919)
  round 1.3 hole 0.8 paste-1000 mask+0: 2(-3.594,8.115) 3(-1.803,6.312) 5(1.803,9.919) 6(3.594,8.115) 7(1.803,6.312)
  round 2.8 hole 1.85 paste-1000 mask+0: A(-6.625,-13.97) B(-3.325,-13.97)
  round 1.05 hole 0.55 paste-1000 mask+0: C(3.075,-13.97) D(5.575,-13.97)
  silkscreen extent -12.45,-11.11 12.45,11.72, body extent -12.55,-30.26 12.55,11.21, height 0.25
FUSE_392 [mm] "LITTELFUSE"
  round 1.7 hole 1.05: 1(-2.54,0) 2(2.54,0)
  silkscreen extent -4.32,-2.03 4.32,2.03, body extent -4.25,-2 4.25,2, height 8
IEC_HighVoltage_Small [mm]
  silkscreen extent -2.72,-2.24 2.72,2.47
IEC_HotSurface_Small [mm]
  silkscreen extent -2.72,-2.36 2.72,2.35
Keystone5010 [mil] "Keystone Multipurpose loops"
  round 87 hole 63: 1(0,0)
  silkscreen extent -70,-70 70,70, body extent -63,-63 63,62, height 319
Keystone5011 [mil] "Keystone Multipurpose loops"
  round 87 hole 63: 1(0,0)
  silkscreen extent -70,-70 70,70, body extent -63,-63 63,62, height 319
Keystone5012 [mil] "Keystone Multipurpose loops"
  round 87 hole 63: 1(0,0)
  silkscreen extent -70,-70 70,70, body extent -63,-63 63,62, height 319
Pb-Free_Overlay_Medium [mm]
  silkscreen extent -2.41,-2.41 2.41,2.41
PG-TDSON-8 [mm] "Infineon recommended land pattern"
  rect 1.2x0.65 smd: 1(-2.825,1.905) 2(-2.825,0.635) 3(-2.825,-0.635) 4(-2.825,-1.905)
  rect 0.5x0.7 smd: 5(3.175,-2) 6(3.175,-0.675) 7(3.175,0.675) 8(3.175,2)
  rect 4.5x4.7 smd paste-2.25: 9(0.675,0)
  silkscreen extent -3.74,-3 3.74,3, body extent -3.18,-2.89 3.18,2.9, height 1.1
Renco_RLTI-1301 [mil] "TH, 4-Leads, Body 15.24x9.906mm"
  rrect50% 48x48 hole 32: 1(-125,200)
  round 48 hole 32: 2(125,200) 3(-125,-200) 4(125,-200)
  body extent -195,-300 195,300, height 725
RTE0016C [mm] "Texas Insturments"
  rrect42% 0.6x0.24 smd: 1(-1.4,0.75) 2(-1.4,0.25) 3(-1.4,-0.25) 4(-1.4,-0.75) 9(1.4,-0.75) 10(1.4,-0.25) 11(1.4,0.25) 12(1.4,0.75)
  rrect42% 0.24x0.6 smd: 5(-0.75,-1.4) 6(-0.25,-1.4) 7(0.25,-1.4) 8(0.75,-1.4) 13(0.75,1.4) 14(0.25,1.4) 15(-0.25,1.4) 16(-0.75,1.4)
  rrect6% 1.55x1.55 on Bottom Paste: 17(0,0)
  rrect6% 1.68x1.68 smd paste-0.85: 17(0,0)
  silkscreen extent -1.72,-1.72 1.72,1.73, body extent -1.5,-1.5 1.5,1.5, height 0.8
SMA [mm] "Molded Diode, 2-Leads, Body 4.3x2.6mm, IPC Medium Density, based on OnSemi component dimensions and land pattern"
  rect 2x2 smd: 1(-2,0) 2(2,0)
  silkscreen extent -3.66,-1.57 2.79,1.57, body extent -2.6,-1.3 2.6,1.3, height 2.42
SOD-123H [mm] "SMT, 2-Leads, Body 3.5x1.6mm"
  rect 1.3x1.8 smd: 1(-1.5,0) 2(1.5,0)
  silkscreen extent -2.9,-1.3 2.3,1.3, body extent -1.9,-0.9 1.9,0.9, height 1
SOD-323 [mm] "NXP recommended land pattern"
  rect 0.6x0.6 smd paste-0.05: 1(-1.1,0) 2(1.1,0)
  silkscreen extent -2.06,-0.86 1.53,0.86, body extent -1.3,-0.67 1.3,0.68, height 1.1
SOD-323-Bi [mm] "SOD323, 2-Leads, Body 1.9x1.45mm, No Polarity Mark"
  rect 0.6x0.6 smd paste-0.05: 1(-1.1,0) 2(1.1,0)
  silkscreen extent -1.53,-0.77 1.53,0.77, body extent -1.27,-0.65 1.27,0.65, height 1.02
SOD-523 [mm] "NXP Semiconductor recommended land pattern, nominal STEP model"
  rect 0.8x0.6 smd paste-0.05: 1(-0.55,0) 2(0.55,0)
  silkscreen extent -1.65,-0.66 1.2,0.66, body extent -0.8,-0.4 0.8,0.4, height 0.72
SOP254P1020X230-4 [mm] "VISHAY"
  rect 1.3x0.9 smd: 1(-4.75,1.27) 2(-4.75,-1.27) 3(4.75,-1.27) 4(4.75,1.27)
  body extent -3.85,-2.05 3.85,2.05, height 2.02
SOT-23L [mm] "SOT23, 3-Leads, Body 2.9x1.3mm, Pitch 0.95mm, Lead Span 2.5mm, IPC High Density"
  rrect50% 0.8x0.6 smd: 1(-1.1,0.95) 2(-1.1,-0.95) 3(1.1,0)
  silkscreen extent -1.5,-1.5 0.7,1.5, body extent -1.16,-1.45 1.21,1.45, height 1
SOT-363 [mm]
  rect 0.6x0.42 smd mask+0.051: 1(-0.95,0.65) 2(-0.95,0) 3(-0.95,-0.65) 4(0.95,-0.65) 5(0.95,0) 6(0.95,0.65)
  silkscreen extent -0.38,-1.02 0.38,1.02, body extent -1.1,-1.1 1.1,1.1, height 1.12
Sullins_GRPB021VWVN-RC [mil] "Sullins"
  rrect10% 41x41 hole 28: 1(-25,0)
  round 41 hole 28: 2(25,0)
  silkscreen extent -70,-42 50,42, body extent -50,-42 50,42, height 157
Sullins_GRPB051VWVN-RC [mm] "SULLINS"
  oval 0.9x1.4 hole 0.7: 1(-2.54,0) 2(-1.27,0) 3(0,0) 4(1.27,0) 5(2.54,0)
  silkscreen extent -3.52,-1.48 3.45,1.2, body extent -3.42,-1.17 3.42,1.17, height 4.2
TUMD2SM [mm] "SMD, 2-Leads, Body 2x1.4mm"
  rrect12% 0.8x1.1 smd: 1(-1.15,0) 2(1.15,0)
  silkscreen extent -2.2,-0.95 1.55,0.95, body extent -1.35,-0.75 1.35,0.75, height 0.8
UPW_500x1100 [mm] "TH, 2-Leads, Dia 5mm,  Lead Spacing 2mm"
  rect 1.25x1.25 hole 0.75: 1(-1,0)
  round 1.25 hole 0.75: 2(1,0)
  silkscreen extent -2.75,-2.75 2.75,2.75, body extent -2.73,-2.75 2.75,2.75, height 12.51
WCAP-FTX2_1300x700x1300 [mm] "TH, 2-Leads, Body 13x7mm, Pin Spacing 10mm"
  round 1.35 hole 0.9: 1(-5,0) 2(5,0)
  body extent -6.5,-3.5 6.5,3.5, height 13
WEEE_Minimum [mm] "WEEElie bin"
  silkscreen extent -2.42,-4.38 2.52,2.65
Wurth_632_723_300_011 [mm] "Connector, Receptacle, USB Type C, R/A"
  rect 0.3x1.2 smd: A1(-2.75,10.58) A2(-2.25,10.58) A3(-1.75,10.58) A4(-1.25,10.58) A5(-0.75,10.58) A6(-0.25,10.58) A7(0.25,10.58) A8(0.75,10.58) A9(1.25,10.58) A10(1.75,10.58) A11(2.25,10.58) A12(2.75,10.58)
  round 0.55 hole 0.4: B1(2.8,9.32) B2(2.4,8.62) B3(1.6,8.62) B4(1.2,9.32) B5(0.8,8.62) B6(0.4,9.32) B7(-0.4,9.32) B8(-0.8,8.62) B9(-1.2,9.32) B10(-1.6,8.62) B11(-2.4,8.62) B12(-2.8,9.32) M1(2,9.32) M2(-2,9.32)
  rrect100% 1x1.6 hole 0.6 slot 1.2 at 90 deg: S1(-4.27,8.18) S2(-4.27,3.45) S3(4.27,3.45) S4(4.27,8.18)
  silkscreen extent -4.37,0.15 4.37,10.36, body extent -4.37,-0.96 4.37,10.83, height 3.07
Z4-D [mm] "SMD, 4-Leads, Body 8.1x10.5mm"
  rect 4.7x2.4 smd: 1(-3.7,2.55) 2(3.7,2.55) 3(3.7,-2.55) 4(-3.7,-2.55)
  silkscreen extent -5.3,-4.1 5.3,4.1, body extent -5.3,-4.1 5.3,4.1, height 1.56

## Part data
C1: library part CMP-0067531-1, "CAP, AL, 39 µF, 400 V, +/- 20%, AEC-Q200 Grade 2, TH", Cap_Case=14.5X20mm, Manufacturer=Chemi-Con, Supplier Part Number 1=565-3520-ND, Tolerance_%=20%, Value1=Unknown, Value2=400V, ValueDisplayed=39µF
C2: library part CMP-0009972-1, "CAP, AL, 68 uF, 400 V, +/- 20%, TH", Cap_Case=18x20mm, Manufacturer=Rubycon, Supplier Part Number 1=1189-1322-ND, Tolerance_%=20%, Value1=Unknown, Value2=400V, ValueDisplayed=68uF
C3: library part CMP-0081647-1, "CAP, Film, 0.1 µF,  V,+/- 10%, TH", Cap_Case=13x7x13mm, Manufacturer="Wurth Elektronik", Supplier Part Number 1=732-5883-ND, Tolerance_%=10%, ValueDisplayed=0.1µF
C4 C5: library part CMP-0009076-1, "CAP, CERM, 0.1 uF, 630 V, +/- 10%, X7R, 1210", Cap_Case=1210, Manufacturer=Kemet, Supplier Part Number 1=399-13490-1-ND, TempCo=X7R, Tolerance_%=10%, Value1=Unknown, Value2=630V, ValueDisplayed=0.1uF
C6: "CAP, CERM, 1000 pF, 630 V,+/- 10%, X7R, 1206", Cap_Case=1206, Manufacturer=MuRata, Supplier Part Number 1=490-3506-1-ND, TempCo=X7R, Tolerance_%=10, Value2=630V, ValueDisplayed=1000pF
C7: library part CMP-0007975-2, "CAP, CERM, 2.2 uF, 25 V, +/- 10%, X7R, AEC-Q200 Grade 1, 0805", Cap_Case=0805, Manufacturer=TDK, Supplier Part Number 1=445-6965-1-ND, TempCo=X7R, Tolerance_%=10%, Value1=Unknown, Value2=25V, ValueDisplayed=2.2uF
C8: library part CMP-0007872-2, "CAP, CERM, 1 uF, 50 V, +/- 10%, X7R, 0805", Cap_Case=0805, Manufacturer=TDK, Supplier Part Number 1=445-14539-1-ND, TempCo=X7R, Tolerance_%=10%, Value1=Unknown, Value2=50V, ValueDisplayed=1uF
C9 C26 C39 C40: library part CMP-0009224-2, "CAP, CERM, 22 uF, 25 V, +/- 10%, X7R, 1210", Cap_Case=1210, Manufacturer=MuRata, Supplier Part Number 1=490-5313-1-ND, TempCo=X7R, Tolerance_%=10%, Value1=Unknown, Value2=25V, ValueDisplayed=22uF
C10 C17: library part CMP-0006675-2, "CAP, CERM, 0.1 uF, 50 V, +/- 20%, X7R, 0402", Cap_Case=0402, Manufacturer=MuRata, Supplier Part Number 1=490-10701-1-ND, TempCo=X7R, Tolerance_%=20%, Value1=Unknown, Value2=50V, ValueDisplayed=0.1uF
C11: library part CMP-0008711-2, "CAP, CERM, 1 uF, 100 V, +/- 20%, X7R, 1206", Cap_Case=1206, Manufacturer=TDK, Supplier Part Number 1=445-4468-1-ND, TempCo=X7R, Tolerance_%=20%, Value1=Unknown, Value2=100V, ValueDisplayed=1uF
C12: library part CMP-0006297-2, "CAP, CERM, 0.1 uF, 50 V, +/- 10%, X7R, 0402", Cap_Case=0402, Manufacturer=TDK, Supplier Part Number 1=445-5932-1-ND, TempCo=X7R, Tolerance_%=10%, Value1="0.039064 ohm", Value2=50V, ValueDisplayed=0.1uF
C13 C14 C19 C21: library part CMP-0006410-2, "CAP, CERM, 100 pF, 50 V, +/- 5%, C0G/NP0, 0402", Cap_Case=0402, Manufacturer=MuRata, Supplier Part Number 1=81-GRM1555C1H101JA1D, TempCo=C0G/NP0, Tolerance_%=5%, Value1=Unknown, Value2=50V, ValueDisplayed=100pF
C15: library part CMP-0086279-1, "CAP CER 2200PF 250V RAD", Cap_Case=9x4mm, Manufacturer=MuRata, TempCo=E, Tolerance_%=20%, Value2=250V, ValueDisplayed=2200pF
C16: library part CMP-0084595-1, "CAP, AL, 4.7 µF, 100 V, +/- 20%, TH", Cap_Case=5x11mm, Manufacturer=Nichicon, Tolerance_%=20%, Value2=100V, ValueDisplayed=4.7µF
C18 C29: library part CMP-0007040-4, "CAP, CERM, 1 uF, 25 V, +/- 10%, X7R, 0603", Cap_Case=0603, Manufacturer=TDK, Supplier Part Number 1=445-5956-1-ND, TempCo=X7R, Tolerance_%=10%, Value1=Unknown, Value2=25V, ValueDisplayed=1uF
C20: library part CMP-0006462-2, "CAP, CERM, 3.3 pF, 50 V, +/- 5%, C0G/NP0, 0402", Cap_Case=0402, Manufacturer=MuRata, Supplier Part Number 1=81-GRM1555C1H3R3CA1D, TempCo=C0G/NP0, Tolerance_%=5%, Value1=Unknown, Value2=50V, ValueDisplayed=3.3pF
C22: library part CMP-0008658-2, "CAP, CERM, 10 uF, 50 V, +/- 10%, X5R, 1206", Cap_Case=1206_180, Manufacturer=TDK, Supplier Part Number 1=445-5998-1-ND, TempCo=X5R, Tolerance_%=10%, Value1="0.002229 ohm", Value2=50V, ValueDisplayed=10uF
C23 C31: library part CMP-0006683-2, "CAP, CERM, 2200 pF, 50 V, +/- 10%, X7R, 0402", Cap_Case=0402, Manufacturer=MuRata, Supplier Part Number 1=490-1305-1-ND, TempCo=X7R, Tolerance_%=10%, Value1=Unknown, Value2=50V, ValueDisplayed=2200pF
C24: library part CMP-0006441-2, "CAP, CERM, 24 pF, 50 V, +/- 5%, C0G/NP0, 0402", Cap_Case=0402, Manufacturer=MuRata, Supplier Part Number 1=81-GRM1555C1H240JA1D, TempCo=C0G/NP0, Tolerance_%=5%, Value1=Unknown, Value2=50V, ValueDisplayed=24pF
C25: library part CMP-0006681-2, "CAP, CERM, 0.018 uF, 50 V, +/- 10%, X7R, 0402", Cap_Case=0402, Manufacturer=MuRata, Supplier Part Number 1=GRM155R71H183KA12D-ND, TempCo=X7R, Tolerance_%=10%, Value1=Unknown, Value2=50V, ValueDisplayed=0.018uF
C27: library part CMP-0006692-2, "CAP, CERM, 4700 pF, 50 V, +/- 10%, X7R, 0402", Cap_Case=0402, Manufacturer=MuRata, Supplier Part Number 1=490-1308-1-ND, TempCo=X7R, Tolerance_%=10%, Value1=Unknown, Value2=50V, ValueDisplayed=4700pF
C28 C30: library part CMP-0006673-2, "CAP, CERM, 1000 pF, 50 V, +/- 10%, X7R, 0402", Cap_Case=0402, Manufacturer=MuRata, Supplier Part Number 1=490-1303-1-ND, TempCo=X7R, Tolerance_%=10%, Value1=Unknown, Value2=50V, ValueDisplayed=1000pF
C32: library part CMP-0008310-2, "CAP, CERM, 10 uF, 35 V, +/- 10%, X5R, 0805", Cap_Case=0805, Manufacturer=MuRata, Supplier Part Number 1=490-10514-1-ND, TempCo=X5R, Tolerance_%=10%, Value1=Unknown, Value2=35V, ValueDisplayed=10uF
